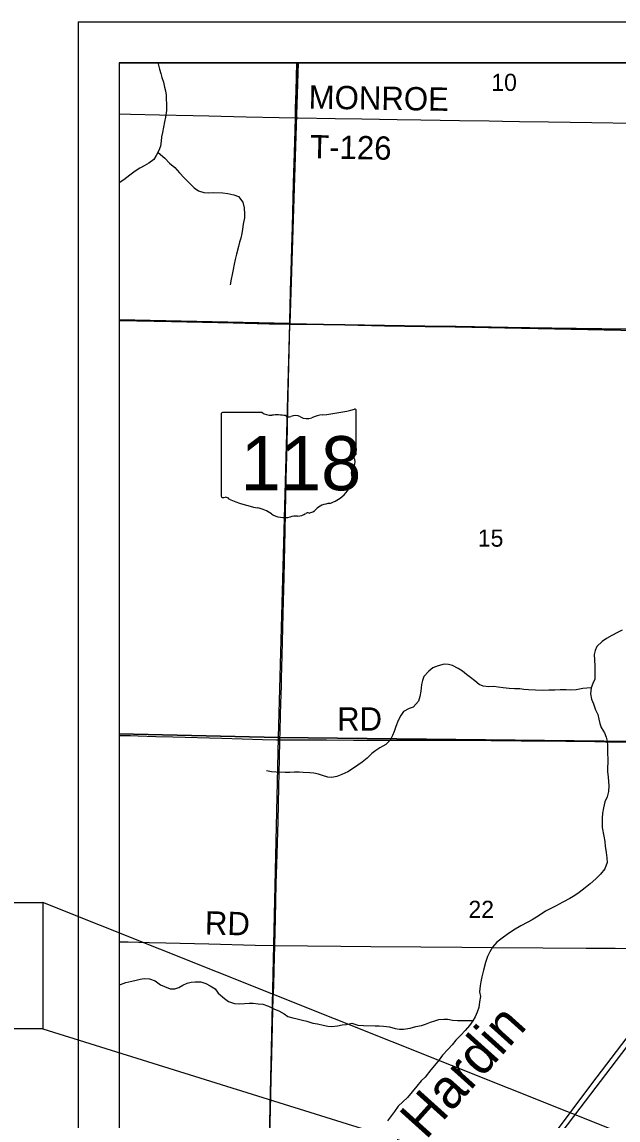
# Model space of a CAD drawing. Extents: x -38.1 to 35.9, y -2.7 to 28.5.
# Drawn here: x 18.373 to 19.827, y 17.155 to 19.831 of the extents above; entities that cross this region are included whole.
import ezdxf

# ---------------------------------------------------------------- set-up
doc = ezdxf.new("R2010")
doc.units = 0
for name, color, linetype in [('GM_X_City_Street_Text', 7, 'Continuous'), ('GM_X_Corporation', 7, 'Continuous'), ('GM_X_County_Road_Text', 7, 'Continuous'), ('GM_X_Interchange_Ramps', 7, 'Continuous'), ('GM_X_Major_River_Text', 7, 'Continuous'), ('GM_X_Minor_Lake', 7, 'Continuous'), ('GM_X_Minor_River', 7, 'Continuous'), ('GM_X_Section', 7, 'Continuous'), ('GM_X_Section_Text', 7, 'Continuous'), ('GM_X_Township', 7, 'Continuous'), ('GM_X_US_Location', 7, 'Continuous'), ('GM_X_US_Route', 7, 'Continuous'), ('SH_Border', 7, 'Continuous'), ('SH_Data', 7, 'Continuous')]:
    doc.layers.add(name, color=color, linetype=linetype)

msp = doc.modelspace()

# ---------------------------------------------------------------- linework, layer by layer
at = {"layer": 'GM_X_City_Street_Text'}
for points in [[(18.6101, 19.6068), (18.6383, 19.6063), (18.7091, 19.6048), (18.7905, 19.6029), (18.8288, 19.602), (18.9203, 19.5998), (19.0005, 19.5978), (19.04, 19.5971)], [(18.6101, 18.0922), (18.6379, 18.0915), (18.6571, 18.0911), (18.7, 18.0898), (18.7416, 18.0888), (18.8609, 18.0854), (18.9597, 18.0823), (18.9943, 18.0815), (19.0025, 18.0814)], [(19.0025, 18.0814), (19.0103, 18.0814), (19.023, 18.0813), (19.0746, 18.0811), (19.1162, 18.0809), (19.1821, 18.0806), (19.2175, 18.0805), (19.2405, 18.0804), (19.2877, 18.0805), (19.3393, 18.0803), (19.3716, 18.0803), (19.4481, 18.0801), (19.5177, 18.0796), (19.5904, 18.0791), (19.6991, 18.078), (19.77, 18.0772), (19.7961, 18.0768), (19.8041, 18.0768)], [(19.8041, 18.0768), (19.834, 18.0765), (19.8943, 18.0758), (19.98, 18.0746), (19.9987, 18.0745), (20.0091, 18.0743)]]:
    msp.add_lwpolyline(points, dxfattribs=at)
at = {"layer": 'GM_X_Corporation'}
for points in [[(18.6101, 15.7069), (18.8445, 16.0191), (18.9897, 16.2122), (19.0483, 16.2903), (19.2337, 16.5376), (19.4121, 16.7756), (19.566, 16.98), (19.763, 17.2432), (19.9196, 17.4482), (20.1512, 17.7579), (20.6767, 18.4541), (21.2204, 19.1713), (21.641, 19.7308)], [(18.6101, 15.3282), (18.8021, 15.6262), (18.9395, 15.8264), (19.0058, 15.9302), (19.0089, 15.9495), (19.0142, 16.0977), (19.0173, 16.1531), (19.0191, 16.1912), (19.0199, 16.2263), (19.0305, 16.2532), (19.2347, 16.519), (19.3429, 16.6685), (19.7347, 17.1834), (19.9115, 17.4163)]]:
    msp.add_lwpolyline(points, dxfattribs=at)
at = {"layer": 'GM_X_Interchange_Ramps'}
for points in [[(19.0264, 19.0946), (19.0266, 19.1038), (19.0274, 19.1361), (19.0284, 19.1765), (19.0295, 19.2225), (19.0311, 19.2803), (19.0326, 19.3331), (19.0335, 19.3654), (19.0357, 19.4384), (19.0377, 19.5118), (19.0386, 19.5385), (19.04, 19.5971), (19.0406, 19.6198), (19.0417, 19.6627), (19.0436, 19.7308)], [(18.9896, 17.5801), (18.9916, 17.6457), (18.9924, 17.6879), (18.9935, 17.7308), (18.995, 17.7774), (18.9978, 17.883), (18.9999, 17.9669), (19.0015, 18.0352), (19.0025, 18.0814), (19.0029, 18.1011), (19.0041, 18.1427), (19.0047, 18.17), (19.0058, 18.2135), (19.0063, 18.2315), (19.0075, 18.2862), (19.0104, 18.3893), (19.0123, 18.4775), (19.0153, 18.5917), (19.0178, 18.718), (19.0191, 18.7745), (19.0196, 18.7987), (19.0207, 18.8472), (19.0216, 18.887), (19.0242, 18.9938), (19.0264, 19.0946)], [(18.9764, 17.0748), (18.9782, 17.1482), (18.98, 17.2128), (18.9809, 17.2588), (18.9815, 17.283), (18.9833, 17.3477), (18.9853, 17.4235), (18.986, 17.4508), (18.9871, 17.4819), (18.9881, 17.5204), (18.9896, 17.5801)]]:
    msp.add_lwpolyline(points, dxfattribs=at)
at = {"layer": 'GM_X_Major_River_Text'}
for points in [[(18.6101, 19.6068), (18.6383, 19.6063), (18.7091, 19.6048), (18.7905, 19.6029), (18.8288, 19.602), (18.9203, 19.5998), (19.0005, 19.5978), (19.04, 19.5971)], [(19.04, 19.5971), (19.0466, 19.597), (19.1367, 19.5954), (19.202, 19.5945), (19.2884, 19.5931), (19.3462, 19.5919), (19.3928, 19.5913), (19.44, 19.5906), (19.5121, 19.5896), (19.545, 19.5892), (19.5867, 19.5884), (19.6575, 19.5871), (19.763, 19.5854), (19.866, 19.5838), (19.9226, 19.5828), (20.0167, 19.5813), (20.0502, 19.5807)], [(18.6101, 19.1031), (18.6535, 19.1022), (18.7386, 19.1005), (18.8883, 19.0973), (18.9759, 19.0954), (19.0062, 19.0948), (19.0264, 19.0946)], [(19.0264, 19.0946), (19.0608, 19.094), (19.1089, 19.0931), (19.1611, 19.0923), (19.2574, 19.0906), (19.3562, 19.0888), (19.4326, 19.0878), (19.4767, 19.0871), (19.5587, 19.086), (19.6656, 19.0844), (19.7246, 19.0835), (19.8508, 19.0817), (19.9415, 19.0804), (19.9612, 19.08)], [(18.6101, 17.5893), (18.6325, 17.5888), (18.6835, 17.5875), (18.7239, 17.5867), (18.8289, 17.584), (18.942, 17.581), (18.9896, 17.5801)], [(18.9896, 17.5801), (19.0699, 17.5795), (19.1507, 17.5787), (19.224, 17.578), (19.3462, 17.577), (19.4458, 17.5757), (19.521, 17.5754), (19.6434, 17.5746), (19.749, 17.5737), (19.8198, 17.5732), (19.9615, 17.5717), (19.9965, 17.5714)]]:
    msp.add_lwpolyline(points, dxfattribs=at)
at = {"layer": 'GM_X_Section'}
for points in [[(18.7048, 19.7308), (18.7053, 19.7291), (18.7088, 19.7161), (18.712, 19.7054), (18.7148, 19.6951), (18.7188, 19.6844), (18.7212, 19.6722), (18.7233, 19.6627), (18.7246, 19.652), (18.7251, 19.6414), (18.7256, 19.6319), (18.726, 19.6148), (18.7234, 19.5985), (18.7209, 19.5872), (18.7183, 19.5747), (18.7157, 19.5611), (18.714, 19.5509), (18.7126, 19.5403), (18.7108, 19.5278), (18.7068, 19.5177), (18.7008, 19.5057), (18.6949, 19.4952), (18.6829, 19.4863), (18.671, 19.4798), (18.661, 19.4743), (18.6498, 19.4669), (18.6363, 19.4574), (18.622, 19.4463), (18.6101, 19.4387)], [(18.7048, 19.5136), (18.7108, 19.5077), (18.7216, 19.4987), (18.7335, 19.4867), (18.7458, 19.4758), (18.7573, 19.463), (18.7692, 19.451), (18.7822, 19.4378), (18.793, 19.4266), (18.8035, 19.4191), (18.8171, 19.415), (18.8281, 19.4144), (18.8414, 19.4148), (18.8634, 19.4144), (18.8756, 19.4126), (18.8899, 19.4096), (18.9013, 19.4055), (18.912, 19.3916), (18.9155, 19.3779), (18.9163, 19.3627), (18.9157, 19.3532), (18.9127, 19.3381), (18.9113, 19.326), (18.9092, 19.3154), (18.9067, 19.3041), (18.9038, 19.2943), (18.9013, 19.2833), (18.8967, 19.2645), (18.893, 19.2516), (18.8908, 19.2403), (18.8883, 19.2271), (18.8857, 19.2157), (18.8836, 19.204), (18.881, 19.19)], [(19.8371, 18.3485), (19.8252, 18.3428), (19.8116, 18.3352), (19.7985, 18.328), (19.7881, 18.3211), (19.7748, 18.309), (19.7707, 18.2992), (19.7685, 18.2894), (19.7692, 18.2758), (19.77, 18.2613), (19.77, 18.2484), (19.7704, 18.2385), (19.7701, 18.2291), (19.7653, 18.2186), (19.7615, 18.2077), (19.7592, 18.1937), (19.7623, 18.1807), (19.7665, 18.1692), (19.7717, 18.1546), (19.7771, 18.1431), (19.7802, 18.1316), (19.7825, 18.1213), (19.7856, 18.1113), (19.7936, 18.0982), (19.7975, 18.0878), (19.8002, 18.0779), (19.8011, 18.068), (19.8012, 18.0578), (19.8012, 18.0471), (19.8016, 18.0357), (19.8007, 18.0043), (19.8026, 17.9905)], [(19.7615, 18.2077), (19.7505, 18.2069), (19.7406, 18.206), (19.7242, 18.2031), (19.712, 18.2027), (19.6999, 18.2034), (19.6854, 18.2035), (19.6729, 18.2027), (19.6577, 18.2024), (19.6413, 18.2017), (19.6258, 18.2025), (19.6087, 18.203), (19.597, 18.2042), (19.5871, 18.2052), (19.5746, 18.2059), (19.5613, 18.2067), (19.5466, 18.2083), (19.5341, 18.2098), (19.5235, 18.2109), (19.5113, 18.2108), (19.4981, 18.212), (19.4879, 18.2161), (19.4779, 18.2251), (19.4672, 18.233), (19.4575, 18.2401), (19.4475, 18.2484), (19.4367, 18.2552), (19.4228, 18.2624), (19.413, 18.265), (19.4024, 18.2656), (19.3879, 18.2615), (19.3752, 18.2566), (19.3651, 18.2489), (19.3529, 18.236), (19.35, 18.2258), (19.3474, 18.216), (19.3458, 18.1998), (19.3431, 18.1869), (19.3401, 18.1756), (19.3272, 18.1612), (19.3172, 18.1573), (19.304, 18.1505), (19.2973, 18.1408), (19.2905, 18.1281), (19.2851, 18.1139), (19.2806, 18.1019), (19.2769, 18.0917), (19.2708, 18.0801), (19.2606, 18.0698), (19.2463, 18.0615), (19.2363, 18.0554), (19.2266, 18.0477), (19.2152, 18.0366), (19.2028, 18.0271)], [(19.2028, 18.0271), (19.1815, 18.0121), (19.1676, 18.0029), (19.1534, 17.9964), (19.1408, 17.9917), (19.1285, 17.9897), (19.1191, 17.9903), (19.1062, 17.9944), (19.0964, 17.9973), (19.0851, 17.9998), (19.0752, 18.0012), (19.0589, 18.0019), (19.049, 18.0025), (19.0376, 18.0024), (19.0266, 18.0019), (19.0155, 18.0017), (18.9931, 18.0022), (18.9817, 18.0036), (18.9696, 18.0058)], [(19.8026, 17.9905), (19.8038, 17.9799), (19.8046, 17.9689), (19.8038, 17.9552), (19.8, 17.942), (19.7947, 17.9301), (19.7909, 17.9158), (19.7886, 17.9025), (19.7878, 17.89), (19.7879, 17.8783), (19.7883, 17.868), (19.7922, 17.8466), (19.7945, 17.8337), (19.7953, 17.8219), (19.7979, 17.8066), (19.799, 17.7937), (19.8002, 17.7827), (19.7948, 17.7669), (19.7842, 17.7539), (19.7728, 17.7429), (19.7584, 17.73), (19.7467, 17.7205), (19.7316, 17.7095), (19.7211, 17.7019), (19.7095, 17.6946), (19.6922, 17.686), (19.674, 17.6763), (19.6613, 17.6691), (19.6501, 17.6637), (19.6342, 17.6532), (19.6172, 17.6423), (19.6071, 17.6373), (19.5894, 17.6283), (19.5716, 17.6175), (19.5561, 17.6065), (19.5444, 17.5978), (19.5312, 17.5879), (19.5203, 17.5761), (19.5138, 17.5645), (19.5086, 17.5533), (19.5039, 17.5386), (19.4988, 17.5202), (19.4949, 17.5036), (19.4923, 17.4915), (19.4905, 17.4817), (19.4889, 17.467)], [(18.6101, 17.4834), (18.614, 17.4849), (18.6263, 17.4895), (18.6409, 17.4932), (18.6516, 17.4959), (18.6615, 17.4983), (18.671, 17.4999), (18.6843, 17.4991), (18.6978, 17.4941), (18.7108, 17.4846), (18.7213, 17.4805), (18.7348, 17.4744), (18.7462, 17.4748), (18.7562, 17.4779), (18.7658, 17.4837), (18.7758, 17.488), (18.7858, 17.4903), (18.7953, 17.4919), (18.8097, 17.4919), (18.8221, 17.4873), (18.8326, 17.4817), (18.8445, 17.4741), (18.8521, 17.4636), (18.8669, 17.451), (18.8773, 17.4439), (18.892, 17.4389), (18.9049, 17.4381), (18.9163, 17.4389), (18.9277, 17.4393), (18.9372, 17.4398), (18.9493, 17.4383), (18.9606, 17.4372), (18.9742, 17.4326), (18.9888, 17.4253), (19, 17.4208), (19.0123, 17.4136), (19.022, 17.4072), (19.0336, 17.4038), (19.0442, 17.4016), (19.0574, 17.3982), (19.0676, 17.3956), (19.0822, 17.3906), (19.0943, 17.3895), (19.1079, 17.386), (19.1188, 17.3834), (19.1286, 17.3824), (19.1424, 17.3842), (19.1542, 17.3865), (19.1637, 17.3874), (19.1777, 17.3906)], [(19.4889, 17.467), (19.4917, 17.4561), (19.4891, 17.4425), (19.4873, 17.4293), (19.4833, 17.4176), (19.4785, 17.4063), (19.4729, 17.3962), (19.4647, 17.3854), (19.4538, 17.3727), (19.4436, 17.3612), (19.4312, 17.3493), (19.4222, 17.3381), (19.4129, 17.3277), (19.3985, 17.3125), (19.3906, 17.3013), (19.3793, 17.2875), (19.3703, 17.2774), (19.3566, 17.2591), (19.3466, 17.2499), (19.336, 17.2376), (19.3247, 17.2231), (19.3134, 17.21), (19.2909, 17.1885), (19.2818, 17.1758), (19.2717, 17.1624), (19.265, 17.1527)], [(19.1775, 17.3907), (19.1919, 17.3859), (19.2064, 17.3852), (19.2345, 17.3846), (19.2443, 17.384), (19.2546, 17.3834), (19.2693, 17.3819), (19.2833, 17.3778), (19.2935, 17.376), (19.3038, 17.3758), (19.3202, 17.3784), (19.3339, 17.3823), (19.3477, 17.3854), (19.3572, 17.3882), (19.3695, 17.3929), (19.3799, 17.3968), (19.3894, 17.3996), (19.4016, 17.4009), (19.4115, 17.4003), (19.4232, 17.3981), (19.4353, 17.397), (19.4456, 17.3972), (19.4733, 17.3969)]]:
    msp.add_lwpolyline(points, dxfattribs=at)
at = {"layer": 'GM_X_Section_Text'}
for p, q in [((18.859, 18.8755), (18.859, 18.6754)), ((18.9588, 18.8789), (18.8622, 18.8789)), ((19.1886, 18.7792), (19.1886, 18.8839)), ((19.1885, 18.7792), (19.1886, 18.7792))]:
    msp.add_line(p, q, dxfattribs=at)
for centre, major_axis, start_param, end_param in [((18.8628, 18.8759), (0.00382, 0), 1.712693, 3.28349), ((18.9817, 18.9021), (0.037, 0), 4.042523, 4.731795), ((18.994, 18.7666), (0.133, 0), 1.404758, 1.657858), ((19.0242, 18.8769), (0.0107, 0), 3.836095, 5.185415), ((19.0399, 18.8538), (0.0222, 0), 0.950623, 2.079405), ((19.0686, 18.8855), (0.0267, 0), 4.081561, 5.145723), ((19.1158, 18.8178), (0.0703, 0), 1.699011, 2.107814), ((19.0712, 19.1517), (0.3495, 0), 4.814394, 5.042369), ((19.1849, 18.8843), (0.00367, 0), 6.141152, 7.989035), ((19.1877, 18.7715), (0.00568, 0), 1.883978, 3.671073), ((19.1516, 18.7583), (0.0341, 0), 5.934695, 6.695948), ((19.1847, 18.7788), (0.00393, 0), 5.05454, 6.418171), ((19.0908, 18.7221), (0.0874, 0), 5.101752, 6.440018), ((19.2017, 18.7354), (0.0248, 0), 2.387724, 3.262537), ((18.8628, 18.6749), (0.00385, 0), 3.00124, 4.508301), ((18.8634, 18.6954), (0.0294, 0), 4.665946, 4.897461), ((18.8694, 18.6638), (0.0106, 0), 0.519207, 1.627899), ((19.0032, 18.8436), (0.2524, 0), 4.195997, 4.488961), ((19.1276, 18.6192), (0.0479, 0), 1.647645, 2.488434), ((18.928, 18.5854), (0.079, 0), 0.823519, 1.323587), ((19.0134, 18.6628), (0.0501, 0), 4.026481, 4.996735), ((19.0423, 18.5936), (0.0412, 0), 1.495662, 1.94098), ((19.046, 18.6478), (0.0267, 0), 4.691044, 5.507374), ((19.0702, 18.6284), (0.00752, 0), 1.147584, 2.315152), ((19.067, 18.656), (0.0282, 0), 4.937069, 5.64225)]:
    msp.add_ellipse(centre, major_axis=major_axis, ratio=0.8, start_param=start_param, end_param=end_param, dxfattribs=at)
at = {"layer": 'GM_X_US_Route'}
for points in [[(19.0472, 19.7308), (18.6101, 19.7308), (18.6101, 19.1047), (19.0268, 19.0959)], [(20.0554, 19.7308), (19.0472, 19.7308), (19.0268, 19.0959), (20.0353, 19.0758)], [(18.6101, 19.1047), (18.6101, 18.0958), (18.9989, 18.0871), (19.0268, 19.0959)], [(19.0268, 19.0959), (20.0353, 19.0758), (20.0086, 18.0758), (18.9989, 18.0871)], [(18.6101, 18.0958), (18.6101, 17.0862), (18.9765, 17.0768), (18.9989, 18.0871)], [(20.0086, 18.0758), (19.9831, 17.0625), (18.9765, 17.0768), (18.9989, 18.0871)]]:
    msp.add_lwpolyline(points, close=True, dxfattribs=at)
for points in [[(25.4101, 19.7308), (18.6101, 19.7308), (18.6101, 19.1036), (18.6533, 19.1027), (18.7384, 19.101), (18.8881, 19.0978), (18.9757, 19.0959), (19.0059, 19.0954), (19.0261, 19.0951), (19.0605, 19.0945), (19.1086, 19.0937), (19.1608, 19.0928), (19.2571, 19.0912), (19.3559, 19.0894), (19.4324, 19.0884), (19.4765, 19.0877), (19.5585, 19.0865), (19.6654, 19.0849), (19.7244, 19.084), (19.8505, 19.0822)], [(19.8505, 19.0822), (19.7244, 19.084), (19.6654, 19.0849), (19.5585, 19.0865), (19.4765, 19.0877), (19.4324, 19.0884), (19.3559, 19.0894), (19.2571, 19.0912), (19.1608, 19.0928), (19.1086, 19.0937), (19.0605, 19.0945), (19.0261, 19.0951), (19.0059, 19.0954), (18.9757, 19.0959), (18.8881, 19.0978), (18.7384, 19.101), (18.6533, 19.1027), (18.6101, 19.1036), (18.6101, 13.5671)]]:
    msp.add_lwpolyline(points, dxfattribs=at)
at = {"layer": 'SH_Border'}
for q in [(18.6101, 12.9308), (25.4101, 19.7308)]:
    msp.add_line((18.6101, 19.7308), q, dxfattribs=at)
at = {"layer": 'SH_Data'}
for q in [(25.5101, 19.8308), (18.5101, 12.8308)]:
    msp.add_line((18.5101, 19.8308), q, dxfattribs=at)
for points in [[(16.722, 17.6847), (18.4243, 17.6847), (18.4243, 17.3766), (16.722, 17.3766)], [(18.4243, 17.3766), (21.976, 16.2689), (18.4243, 17.6847)]]:
    msp.add_lwpolyline(points, close=True, dxfattribs=at)

# ---------------------------------------------------------------- texts
at = {"layer": 'GM_X_County_Road_Text'}
for s in ['s', 'r']:
    msp.add_text(s, height=0.000189, dxfattribs=at).set_placement((19.0201, 18.7621))
msp.add_text('118', height=0.000189, rotation=0, dxfattribs=at).set_placement((18.9532, 18.7483))
at = {"layer": 'GM_X_Minor_Lake'}
for s, rotation, p in [('MONROE', 359.0531, (19.072, 19.6196)), ('T-126', 358.8752, (19.0755, 19.4986)), ('RD', 358.5194, (18.8188, 17.6071))]:
    msp.add_text(s, height=0.05682, rotation=rotation, dxfattribs=at).set_placement(p)
at = {"layer": 'GM_X_Minor_River'}
for s, p in [('10', (19.5178, 19.6627)), ('15', (19.4849, 18.552)), ('22', (19.462, 17.6472))]:
    msp.add_text(s, height=0.04186, rotation=0, dxfattribs=at).set_placement(p)
at = {"layer": 'GM_X_Section_Text'}
msp.add_text('118', height=0.13184, dxfattribs=at).set_placement((18.9066, 18.6895))
at = {"layer": 'GM_X_Township'}
msp.add_text('RD', height=0.05682, rotation=0, dxfattribs=at).set_placement((19.1416, 18.1037))
at = {"layer": 'GM_X_US_Location'}
msp.add_text('Hardin', height=0.09468, rotation=48.0207, dxfattribs=at).set_placement((19.358, 17.1045))

doc.saveas('drawing.dxf')
